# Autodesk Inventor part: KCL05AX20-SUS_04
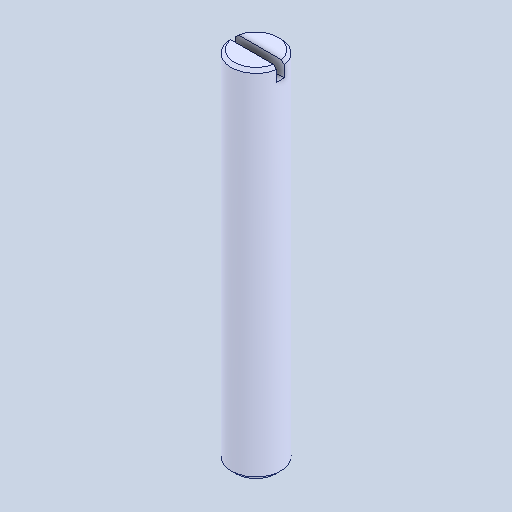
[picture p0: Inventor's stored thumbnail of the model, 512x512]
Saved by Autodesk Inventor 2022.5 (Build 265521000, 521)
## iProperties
Created: 2024-08
Part Number: KCL05AX20-SUS_04
Material: 一般
Document SubType Name: Modeling
Designer: ImaoCorp
Density: 1 g/cm^3
Appearance: 既定
Author: ImaoCorp
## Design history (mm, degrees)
feature "KCL05AX20-SUS_04"
node "ソリッド1"
